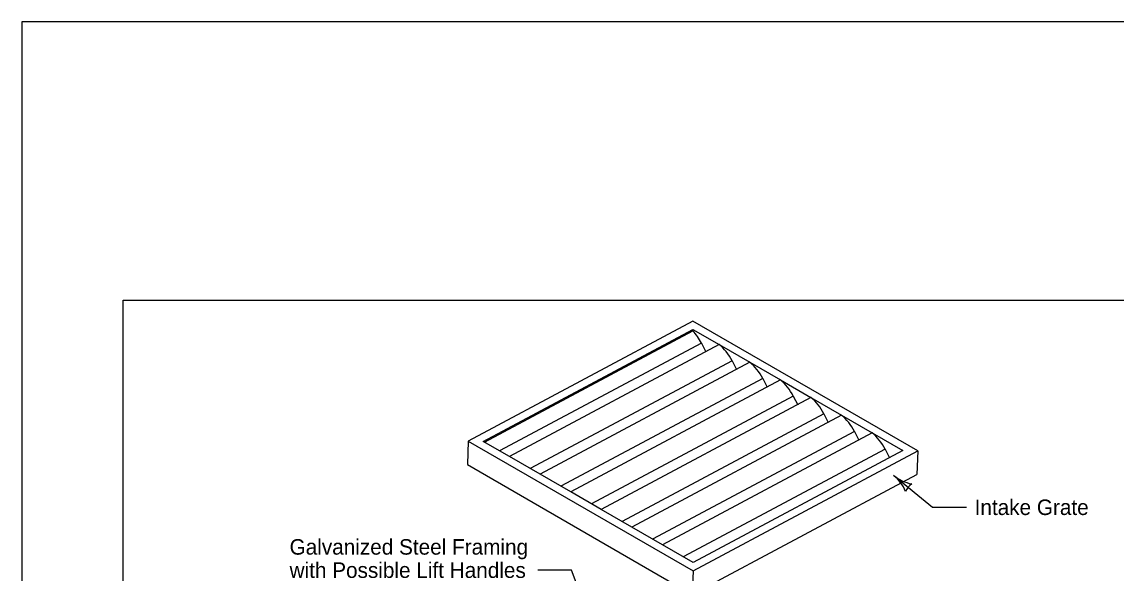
# Model space of a CAD drawing. Extents: x -4827 to -1483, y 910 to 4235.
# Drawn here: x -4827 to -3698, y 2925 to 3494 of the extents above; entities that cross this region are included whole.
import ezdxf

# ---------------------------------------------------------------- set-up
doc = ezdxf.new("R2010")
doc.units = 0
for name, color, linetype in [('Default', 7, 'Continuous'), ('dsnShtPlotShapeBatchPrint', 7, 'Continuous'), ('dsnStdBlock', 7, 'Continuous'), ('dsnStdBorder', 7, 'Continuous'), ('dsnStdLabel', 7, 'Continuous'), ('dsnStdNote', 7, 'Continuous')]:
    doc.layers.add(name, color=color, linetype=linetype)

msp = doc.modelspace()

# ---------------------------------------------------------------- linework, layer by layer
at = {"layer": 'Default'}
for p, q in [((-4134.7, 3185.5), (-4366.6, 3061.7)), ((-3902.7, 3051.5), (-4134.7, 3185.5)), ((-4351.1, 3061.3), (-4134.7, 3176.9)), ((-4350, 3060.6), (-4134.8, 3175.5)), ((-4134.7, 3176.9), (-4134.8, 3175.5)), ((-4134.7, 3176.9), (-4107.7, 3161.3)), ((-4125.9, 3162.8), (-4334.2, 3051.5)), ((-4125.9, 3162.8), (-4121.4, 3153.9)), ((-4107.7, 3161.3), (-4324.1, 3045.7)), ((-4107.7, 3161.3), (-4076.1, 3143)), ((-4094.3, 3144.5), (-4302.6, 3033.3)), ((-4076.1, 3143), (-4292.5, 3027.5)), ((-4094.3, 3144.5), (-4089.8, 3135.7)), ((-4076.1, 3143), (-4044.5, 3124.8)), ((-4062.7, 3126.3), (-4271, 3015.1)), ((-4044.5, 3124.8), (-4260.9, 3009.2)), ((-4062.7, 3126.3), (-4058.2, 3117.5)), ((-4044.5, 3124.8), (-4012.9, 3106.6)), ((-4031.2, 3108.1), (-4239.4, 2996.8)), ((-4012.9, 3106.6), (-4229.3, 2991)), ((-4031.2, 3108.1), (-4026.6, 3099.2)), ((-4012.9, 3106.6), (-3981.3, 3088.3)), ((-3999.6, 3089.8), (-4207.9, 2978.6)), ((-3981.3, 3088.3), (-4197.7, 2972.8)), ((-3999.6, 3089.8), (-3995.1, 3081)), ((-3981.3, 3088.3), (-3949.8, 3070.1)), ((-4366.6, 3061.7), (-4367.4, 3037.4)), ((-4366.6, 3061.7), (-4134.6, 2927.7)), ((-4324.1, 3045.7), (-4351.1, 3061.3)), ((-3968, 3071.6), (-4176.3, 2960.4)), ((-3949.8, 3070.1), (-4166.2, 2954.5)), ((-3968, 3071.6), (-3963.5, 3062.8)), ((-3949.8, 3070.1), (-3918.2, 3051.9)), ((-3936.4, 3053.4), (-4144.7, 2942.1)), ((-3918.2, 3051.9), (-4134.6, 2936.3)), ((-4134.6, 2927.7), (-3902.7, 3051.5)), ((-3936.4, 3053.4), (-3931.9, 3044.5)), ((-3902.7, 3051.5), (-3903.5, 3027.3)), ((-4292.5, 3027.5), (-4324.1, 3045.7)), ((-4367.4, 3037.4), (-4135.4, 2903.5)), ((-4260.9, 3009.2), (-4292.5, 3027.5)), ((-4135.4, 2903.5), (-3903.5, 3027.3)), ((-4229.3, 2991), (-4260.9, 3009.2)), ((-4197.7, 2972.8), (-4229.3, 2991)), ((-4166.2, 2954.5), (-4197.7, 2972.8)), ((-4134.6, 2936.3), (-4166.2, 2954.5)), ((-4134.6, 2927.7), (-4135.4, 2903.5))]:
    msp.add_line(p, q, dxfattribs=at)
for centre, end_param in [((-4143.1, 3155.9), 2.022613), ((-4111.5, 3137.7), 2.236918), ((-4079.9, 3119.4), 2.236918), ((-4048.3, 3101.2), 2.236918), ((-4016.7, 3083), 2.236918), ((-3985.2, 3064.7), 2.236918), ((-3953.6, 3046.5), 2.236918)]:
    msp.add_ellipse(centre, major_axis=(14.5, -27.1), ratio=0.59858, start_param=1.504307, end_param=end_param, dxfattribs=at)
at = {"layer": 'dsnShtPlotShapeBatchPrint'}
msp.add_lwpolyline([(-4827.3, 910.3), (-1483.3, 910.3), (-1483.3, 3494.3), (-4827.3, 3494.3)], close=True, dxfattribs=at)
at = {"layer": 'dsnStdBlock'}
for points in [[(-3927.5, 3026.3), (-3887.4, 2993.4), (-3852.4, 2993.4)], [(-4239.1, 2872.6), (-4259.9, 2928.5), (-4294.9, 2928.5)]]:
    msp.add_lwpolyline(points, dxfattribs=at)
at = {"layer": 'dsnStdBorder'}
msp.add_lwpolyline([(-4722.8, 3207.3), (-1587.8, 3207.3), (-1587.8, 1197.3), (-4722.8, 1197.3)], close=True, dxfattribs=at)
at = {"layer": 'dsnStdLabel'}
for centre, radius, start, end in [((-3900.6, 3059.2), 42.5, 230.6885, 258.761), ((-3954.5, 2993.4), 42.5, 22.616, 50.6885), ((-3900, 3003.7), 16.4, 122.9551, 158.4218)]:
    msp.add_arc(centre, radius, start, end, dxfattribs=at)

# ---------------------------------------------------------------- texts
at = {"layer": 'dsnStdNote'}
for s, p in [('Intake Grate', (-3844, 2985.4)), ('Galvanized Steel Framing', (-4551, 2944.5)), ('with Possible Lift Handles', (-4551, 2920.5))]:
    msp.add_text(s, height=16, dxfattribs=at).set_placement(p)

doc.saveas('drawing.dxf')
